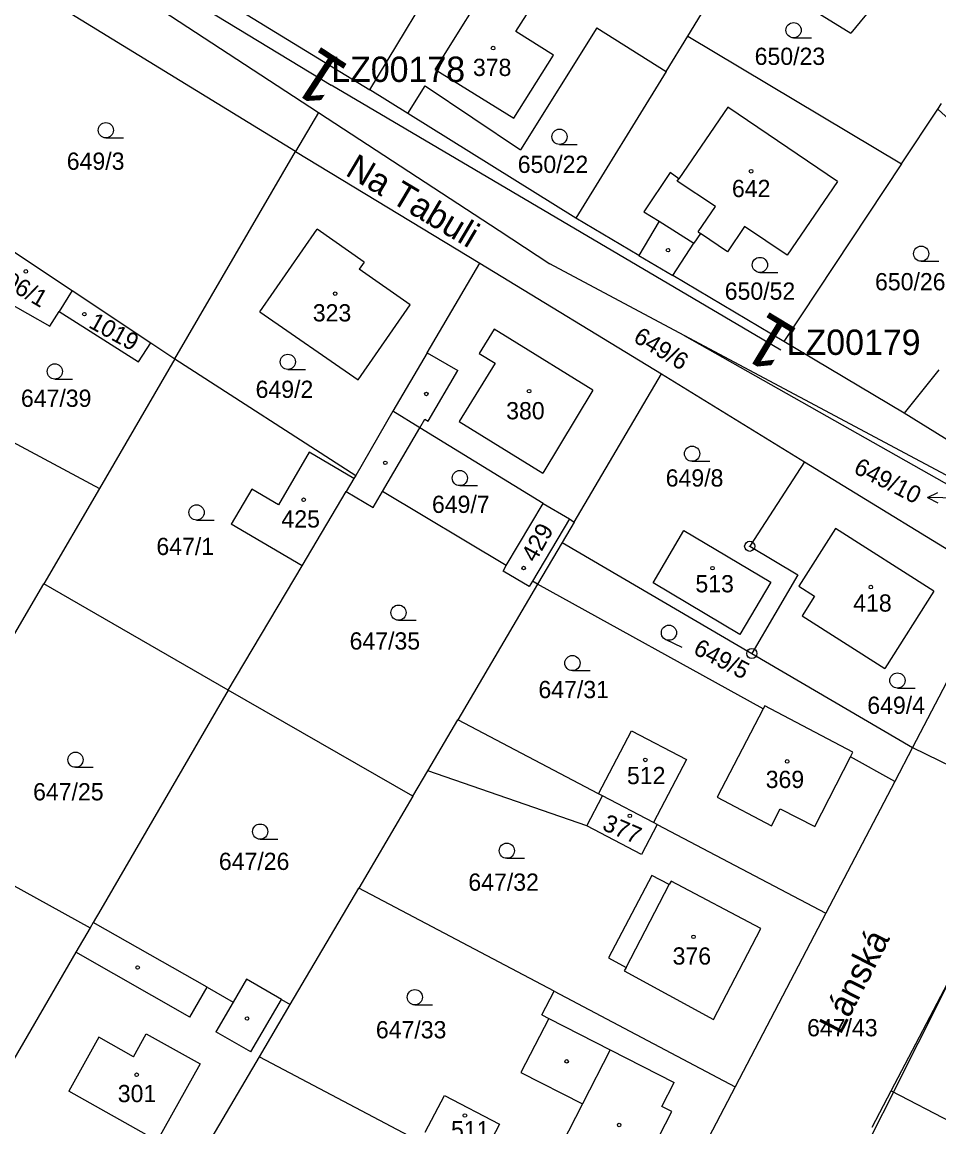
# Model space of a CAD drawing. Extents: x -738131 to -734179, y -1033447 to -1030078.
# Drawn here: x -735990.9 to -735900.5, y -1032576 to -1032467.1 of the extents above; entities that cross this region are included whole.
import ezdxf

# ---------------------------------------------------------------- set-up
doc = ezdxf.new("R2010")
doc.units = 0
for name, color, linetype in [('ftf_2010', 7, 'Continuous'), ('ftf_3010', 7, 'Continuous'), ('ftf_3010_ftf_3010_gtda_3015_gtda_3015_1', 7, 'Continuous'), ('ftf_nu', 7, 'Continuous'), ('Vrstva 1', 7, 'Continuous'), ('Vrstva 2', 7, 'Continuous'), ('Vrstva 3', 7, 'Continuous'), ('Vrstva 4', 7, 'Continuous'), ('Vrstva 5', 7, 'Continuous'), ('Vrstva 7', 7, 'Continuous'), ('Vrstva 8', 7, 'Continuous')]:
    doc.layers.add(name, color=color, linetype=linetype)

msp = doc.modelspace()

# ---------------------------------------------------------------- linework, layer by layer
at = {"layer": 'ftf_2010'}
for points in [[(-735998.88, -1032445.56), (-735998.88, -1032446.09), (-736000.43, -1032449.03), (-735960.4, -1032473.34)], [(-735916.05, -1032499.44), (-735960.4, -1032473.34)], [(-735895.6, -1032554), (-735909.49, -1032581.62)]]:
    msp.add_lwpolyline(points, dxfattribs=at)
at = {"layer": 'Vrstva 1'}
for points in [[(-736001.29, -1032450.11), (-735961.65, -1032476.02)], [(-735963.89, -1032479.87), (-736004.16, -1032455.17)], [(-735899.3, -1032456.19), (-735909.16, -1032468.19)], [(-735956.57, -1032473.77), (-735948.6, -1032460.55)], [(-735977.39, -1032461.05), (-735956.57, -1032473.77)], [(-735918.63, -1032462.31), (-735909.16, -1032468.19)], [(-735925.22, -1032468.51), (-735923.86, -1032466.3)], [(-735934.2, -1032467.66), (-735941.72, -1032479.7)], [(-735934.2, -1032467.66), (-735927.34, -1032471.97)], [(-735927.34, -1032471.97), (-735925.22, -1032468.51)], [(-735925.22, -1032468.51), (-735904.14, -1032481.08)], [(-735927.34, -1032471.97), (-735936.25, -1032486.44)], [(-735952.82, -1032476.11), (-735956.57, -1032473.77)], [(-735952.82, -1032476.11), (-735951.13, -1032473.4)], [(-735951.13, -1032473.4), (-735941.72, -1032479.7)], [(-735961.65, -1032476.02), (-735963.89, -1032479.87)], [(-735961.65, -1032476.02), (-735943.83, -1032487.67)], [(-735936.25, -1032486.44), (-735952.82, -1032476.11)], [(-735921.28, -1032475.49), (-735926.09, -1032482.55)], [(-735910.47, -1032482.83), (-735921.28, -1032475.49)], [(-735904.14, -1032481.08), (-735900.58, -1032475.7)], [(-735900.58, -1032475.7), (-735900.2, -1032475.13)], [(-735900.58, -1032475.7), (-735895.38, -1032480.43)], [(-735975.8, -1032500.31), (-735963.89, -1032479.87)], [(-735963.89, -1032479.87), (-735945.72, -1032490.89)], [(-735904.14, -1032481.08), (-735915.75, -1032498.6)], [(-735926.97, -1032481.94), (-735929.55, -1032485.8)], [(-735926.09, -1032482.55), (-735926.97, -1032481.94)], [(-735910.47, -1032482.83), (-735915.41, -1032490.1)], [(-735929.55, -1032485.8), (-735928.03, -1032486.75)], [(-735930.05, -1032490.12), (-735936.25, -1032486.44)], [(-735928.03, -1032486.75), (-735930.05, -1032490.12)], [(-735967.43, -1032495.67), (-735961.78, -1032487.53)], [(-735957.12, -1032490.76), (-735961.78, -1032487.53)], [(-735943.83, -1032487.67), (-735938.83, -1032490.94)], [(-735923.96, -1032487.95), (-735924.62, -1032488.91)], [(-735921.3, -1032489.77), (-735923.96, -1032487.95)], [(-735919.62, -1032487.26), (-735921.3, -1032489.77)], [(-735915.41, -1032490.1), (-735919.62, -1032487.26)], [(-735993.94, -1032488.26), (-735990.54, -1032490.52)], [(-735926.71, -1032492.09), (-735924.62, -1032488.91)], [(-735930.05, -1032490.12), (-735926.71, -1032492.09)], [(-735990.54, -1032490.52), (-735985.92, -1032493.57)], [(-735957.12, -1032490.76), (-735957.62, -1032491.48)], [(-735950.91, -1032499.7), (-735945.72, -1032490.89)], [(-735945.72, -1032490.89), (-735927.82, -1032501.78)], [(-735925.59, -1032497.99), (-735938.83, -1032490.94)], [(-735952.59, -1032494.97), (-735957.62, -1032491.48)], [(-735915.75, -1032498.6), (-735926.71, -1032492.09)], [(-735992.53, -1032494.58), (-735988.14, -1032497.07)], [(-735985.92, -1032493.57), (-735987.22, -1032495.63)], [(-735985.92, -1032493.57), (-735978.16, -1032498.72)], [(-735988.14, -1032497.07), (-735987.22, -1032495.63)], [(-735987.22, -1032495.63), (-735979.37, -1032500.6)], [(-735967.43, -1032495.67), (-735957.74, -1032502.39)], [(-735957.74, -1032502.39), (-735952.59, -1032494.97)], [(-735979.37, -1032500.6), (-735978.16, -1032498.72)], [(-735978.16, -1032498.72), (-735975.8, -1032500.31)], [(-735925.59, -1032497.99), (-735891.4, -1032517.34)], [(-735890.87, -1032516.5), (-735925.59, -1032497.99)], [(-735903.89, -1032505.65), (-735915.75, -1032498.6)], [(-735950.91, -1032499.7), (-735954.32, -1032505.48)], [(-735975.8, -1032500.31), (-735983.24, -1032513.09)], [(-735975.8, -1032500.31), (-735957.97, -1032511.8)], [(-735936.43, -1032516.41), (-735927.82, -1032501.78)], [(-735927.82, -1032501.78), (-735913.7, -1032510.45)], [(-735900.46, -1032501.38), (-735903.89, -1032505.65)], [(-735997.79, -1032505.3), (-735983.24, -1032513.09)], [(-735954.32, -1032505.48), (-735957.97, -1032511.8)], [(-735951.65, -1032507.12), (-735954.32, -1032505.48)], [(-735889.62, -1032514.52), (-735903.89, -1032505.65)], [(-735939.48, -1032514.57), (-735951.65, -1032507.12)], [(-735962.55, -1032509.52), (-735965.59, -1032514.69)], [(-735958.15, -1032512.1), (-735962.55, -1032509.52)], [(-735913.7, -1032510.45), (-735919.12, -1032518.79)], [(-735913.7, -1032510.45), (-735894.48, -1032522.24)], [(-735957.97, -1032511.8), (-735958.15, -1032512.1)], [(-735983.24, -1032513.09), (-735988.72, -1032522.5)], [(-735958.15, -1032512.1), (-735958.92, -1032513.4)], [(-735968.2, -1032513.15), (-735970.24, -1032516.61)], [(-735965.59, -1032514.69), (-735968.2, -1032513.15)], [(-735963.26, -1032520.72), (-735958.92, -1032513.4)], [(-735958.92, -1032513.4), (-735956.26, -1032514.96)], [(-735956.26, -1032514.96), (-735955.33, -1032513.38)], [(-735943.12, -1032520.68), (-735955.33, -1032513.38)], [(-735943.12, -1032520.68), (-735939.48, -1032514.57)], [(-735939.48, -1032514.57), (-735936.9, -1032516.09)], [(-735936.43, -1032516.41), (-735937.61, -1032518.41)], [(-735936.9, -1032516.09), (-735936.43, -1032516.41)], [(-735963.26, -1032520.72), (-735970.24, -1032516.61)], [(-735928.65, -1032522.38), (-735925.6, -1032517.24)], [(-735925.6, -1032517.24), (-735917.04, -1032522.33)], [(-735910.67, -1032517.05), (-735914.27, -1032522.72)], [(-735900.95, -1032523.22), (-735910.67, -1032517.05)], [(-735937.61, -1032518.41), (-735940.03, -1032522.53)], [(-735937.61, -1032518.41), (-735918.91, -1032529.36)], [(-735919.12, -1032518.79), (-735914.36, -1032521.61)], [(-735970.53, -1032532.97), (-735963.26, -1032520.72)], [(-735943.44, -1032521.23), (-735943.12, -1032520.68)], [(-735940.86, -1032522.75), (-735943.44, -1032521.23)], [(-735914.36, -1032521.61), (-735918.91, -1032529.36)], [(-735992.95, -1032529.75), (-735988.72, -1032522.5)], [(-735970.53, -1032532.97), (-735988.72, -1032522.5)], [(-735940.03, -1032522.53), (-735947.89, -1032535.89)], [(-735940.55, -1032522.22), (-735940.86, -1032522.75)], [(-735940.03, -1032522.53), (-735940.55, -1032522.22)], [(-735917.79, -1032534.8), (-735940.03, -1032522.53)], [(-735920.09, -1032527.47), (-735928.65, -1032522.38)], [(-735917.04, -1032522.33), (-735920.09, -1032527.47)], [(-735914.27, -1032522.72), (-735912.72, -1032523.71)], [(-735894.48, -1032522.24), (-735903.06, -1032538.63)], [(-735912.72, -1032523.71), (-735913.96, -1032525.64)], [(-735900.95, -1032523.22), (-735905.79, -1032530.85)], [(-735913.96, -1032525.64), (-735905.79, -1032530.85)], [(-735918.91, -1032529.36), (-735903.06, -1032538.63)], [(-735970.53, -1032532.97), (-735983.11, -1032554.59)], [(-735952.34, -1032543.44), (-735970.53, -1032532.97)], [(-735917.79, -1032534.8), (-735922.32, -1032543.53)], [(-735917.64, -1032534.52), (-735917.79, -1032534.8)], [(-735908.95, -1032539.07), (-735917.64, -1032534.52)], [(-735950.85, -1032540.92), (-735947.89, -1032535.89)], [(-735934.03, -1032543.18), (-735947.89, -1032535.89)], [(-735934.03, -1032543.18), (-735930.76, -1032536.97)], [(-735930.76, -1032536.97), (-735925.34, -1032539.82)], [(-735909.19, -1032539.55), (-735908.95, -1032539.07)], [(-735903.06, -1032538.63), (-735904.8, -1032541.97)], [(-735903.06, -1032538.63), (-735896.53, -1032541.81)], [(-735925.34, -1032539.82), (-735928.61, -1032546.03)], [(-735912.71, -1032546.42), (-735909.19, -1032539.55)], [(-735904.8, -1032541.97), (-735909.19, -1032539.55)], [(-735952.34, -1032543.44), (-735950.85, -1032540.92)], [(-735935.17, -1032546.35), (-735950.85, -1032540.92)], [(-735904.8, -1032541.97), (-735911.61, -1032554.97)], [(-735952.34, -1032543.44), (-735957.67, -1032552.5)], [(-735933.62, -1032543.39), (-735934.03, -1032543.18)], [(-735928.61, -1032546.03), (-735933.62, -1032543.39)], [(-735922.32, -1032543.53), (-735916.96, -1032546.34)], [(-735916.96, -1032546.34), (-735916.11, -1032544.68)], [(-735916.11, -1032544.68), (-735912.71, -1032546.42)], [(-736002.55, -1032546.24), (-735984.16, -1032556.39)], [(-735929.78, -1032549.17), (-735935.17, -1032546.35)], [(-735928.24, -1032546.23), (-735929.78, -1032549.17)], [(-735928.24, -1032546.23), (-735928.61, -1032546.03)], [(-735928.24, -1032546.23), (-735911.61, -1032554.97)], [(-735928.78, -1032551.24), (-735933.05, -1032559.36)], [(-735927.06, -1032552.14), (-735928.78, -1032551.24)], [(-735926.87, -1032551.79), (-735927.06, -1032552.14)], [(-735918.03, -1032556.46), (-735926.87, -1032551.79)], [(-735964.43, -1032563.97), (-735957.67, -1032552.5)], [(-735938.41, -1032562.66), (-735957.67, -1032552.5)], [(-735983.11, -1032554.59), (-735983.86, -1032555.88)], [(-735911.61, -1032554.97), (-735920.55, -1032572.07)], [(-735984.16, -1032556.39), (-735985.57, -1032558.82)], [(-735983.86, -1032555.88), (-735984.16, -1032556.39)], [(-735972.62, -1032562.25), (-735983.86, -1032555.88)], [(-735922.7, -1032565.43), (-735918.03, -1032556.46)], [(-735985.57, -1032558.82), (-735994.48, -1032574.13)], [(-735933.05, -1032559.36), (-735931.29, -1032560.31)], [(-735931.29, -1032560.31), (-735931.49, -1032560.66)], [(-735931.49, -1032560.66), (-735922.7, -1032565.43)], [(-735905.17, -1032572.46), (-735898.9, -1032560.5)], [(-735968.75, -1032561.47), (-735970.05, -1032563.72)], [(-735965.29, -1032563.47), (-735968.75, -1032561.47)], [(-735972.62, -1032562.25), (-735970.05, -1032563.72)], [(-735939.6, -1032564.98), (-735938.41, -1032562.66)], [(-735938.41, -1032562.66), (-735920.55, -1032572.07)], [(-735967.45, -1032569.11), (-735964.43, -1032563.97)], [(-735965.29, -1032563.47), (-735964.43, -1032563.97)], [(-735938.93, -1032565.33), (-735941.67, -1032570.66)], [(-735939.6, -1032564.98), (-735938.93, -1032565.33)], [(-735976.46, -1032584.42), (-735967.45, -1032569.11)], [(-735967.45, -1032569.11), (-735933.28, -1032587.17)], [(-735941.67, -1032570.66), (-735935.62, -1032573.77)], [(-735951.11, -1032576.56), (-735949.21, -1032572.93)], [(-735949.21, -1032572.93), (-735943.78, -1032575.77)], [(-735920.55, -1032572.07), (-735929.5, -1032589.17)], [(-735907.05, -1032576.05), (-735905.17, -1032572.46)], [(-735905.17, -1032572.46), (-735899.23, -1032575.58)], [(-735935.62, -1032573.77), (-735938.38, -1032579.15)], [(-735943.78, -1032575.77), (-735945.69, -1032579.42)]]:
    msp.add_lwpolyline(points, dxfattribs=at)
at = {"layer": 'Vrstva 3'}
for p, q in [((-735914.79, -1032468.66), (-735913.04, -1032468.66)), ((-735982.61, -1032478.52), (-735980.86, -1032478.52)), ((-735937.87, -1032479.16), (-735936.12, -1032479.16)), ((-735902.21, -1032490.69), (-735900.46, -1032490.69)), ((-735918.11, -1032491.8), (-735916.36, -1032491.8)), ((-735964.66, -1032501.35), (-735962.91, -1032501.35)), ((-735987.64, -1032502.3), (-735985.89, -1032502.3)), ((-735924.8, -1032510.41), (-735923.05, -1032510.41)), ((-735947.7, -1032512.81), (-735945.95, -1032512.81)), ((-735973.66, -1032516.2), (-735971.91, -1032516.2)), ((-735953.75, -1032526.08), (-735952, -1032526.08)), ((-735927.4, -1032527.98), (-735925.82, -1032528.73)), ((-735936.6, -1032531.05), (-735934.85, -1032531.05)), ((-735904.55, -1032532.77), (-735902.8, -1032532.77)), ((-735985.6, -1032540.58), (-735983.85, -1032540.58)), ((-735967.39, -1032547.67), (-735965.64, -1032547.67)), ((-735943.07, -1032549.55), (-735941.32, -1032549.55)), ((-735952.14, -1032564), (-735950.39, -1032564))]:
    msp.add_line(p, q, dxfattribs=at)
for centre in [(-735914.79, -1032467.91), (-735982.61, -1032477.77), (-735937.87, -1032478.41), (-735902.21, -1032489.94), (-735918.11, -1032491.05), (-735964.66, -1032500.6), (-735987.64, -1032501.55), (-735924.8, -1032509.66), (-735947.7, -1032512.06), (-735973.66, -1032515.45), (-735953.75, -1032525.33), (-735927.08, -1032527.31), (-735936.6, -1032530.3), (-735904.55, -1032532.02), (-735985.6, -1032539.83), (-735967.39, -1032546.92), (-735943.07, -1032548.8), (-735952.14, -1032563.25)]:
    msp.add_circle(centre, 0.75, dxfattribs=at)
at = {"layer": 'Vrstva 4'}
for points in [[(-735950.13, -1032471.78), (-735943.91, -1032461.81)], [(-735942.17, -1032468.04), (-735939.86, -1032464.35)], [(-735938.48, -1032470.36), (-735942.17, -1032468.04)], [(-735942.36, -1032476.58), (-735938.48, -1032470.36)], [(-735950.13, -1032471.78), (-735942.36, -1032476.58)], [(-735926.26, -1032482.79), (-735926.09, -1032482.55)], [(-735922.5, -1032485.3), (-735926.26, -1032482.79)], [(-735924.21, -1032487.79), (-735922.5, -1032485.3)], [(-735928.03, -1032486.75), (-735924.62, -1032488.91)], [(-735924.21, -1032487.79), (-735923.96, -1032487.95)], [(-735944.3, -1032497.37), (-735945.78, -1032499.77)], [(-735942.76, -1032498.34), (-735944.3, -1032497.37)], [(-735934.6, -1032503.39), (-735942.76, -1032498.34)], [(-735950.91, -1032499.7), (-735947.9, -1032501.47)], [(-735945.78, -1032499.77), (-735944.21, -1032500.73)], [(-735944.21, -1032500.73), (-735947.76, -1032506.49)], [(-735950.82, -1032506.44), (-735947.9, -1032501.47)], [(-735934.6, -1032503.39), (-735939.51, -1032511.58)], [(-735951.65, -1032507.12), (-735951.14, -1032506.25)], [(-735951.14, -1032506.25), (-735950.82, -1032506.44)], [(-735947.76, -1032506.49), (-735939.51, -1032511.58)], [(-735955.33, -1032513.38), (-735951.65, -1032507.12)], [(-735936.9, -1032516.09), (-735940.55, -1032522.22)], [(-735935.17, -1032546.35), (-735933.62, -1032543.39)], [(-735931.29, -1032560.31), (-735927.06, -1032552.14)], [(-735974.31, -1032565.21), (-735985.57, -1032558.82)], [(-735974.31, -1032565.21), (-735972.62, -1032562.25)], [(-735970.05, -1032563.72), (-735971.76, -1032566.66)], [(-735968.31, -1032568.62), (-735965.29, -1032563.47)], [(-735938.93, -1032565.33), (-735932.88, -1032568.44)], [(-735983.29, -1032567.2), (-735986.27, -1032572.52)], [(-735979.89, -1032569.11), (-735983.29, -1032567.2)], [(-735979.89, -1032569.11), (-735978.62, -1032566.84)], [(-735978.62, -1032566.84), (-735973.3, -1032569.82)], [(-735968.31, -1032568.62), (-735971.76, -1032566.66)], [(-735932.88, -1032568.44), (-735935.62, -1032573.77)], [(-735932.88, -1032568.44), (-735926.58, -1032571.67)], [(-735973.3, -1032569.82), (-735977.55, -1032577.41)], [(-735927.78, -1032574.01), (-735926.58, -1032571.67)], [(-735977.55, -1032577.41), (-735986.27, -1032572.52)], [(-735926.78, -1032574.52), (-735927.78, -1032574.01)], [(-735931.09, -1032582.9), (-735926.78, -1032574.52)]]:
    msp.add_lwpolyline(points, dxfattribs=at)
at = {"layer": 'Vrstva 5'}
for centre in [(-735944.42, -1032469.67), (-735918.98, -1032481.81), (-735927.17, -1032489.59), (-735990.5, -1032491.69), (-735959.99, -1032493.88), (-735984.72, -1032495.9), (-735940.87, -1032503.5), (-735951, -1032503.77), (-735955.05, -1032510.56), (-735963.1, -1032514.2), (-735941.41, -1032520.93), (-735922.79, -1032520.94), (-735907.17, -1032522.81), (-735929.41, -1032539.85), (-735915.42, -1032540), (-735930.94, -1032545.36), (-735924.66, -1032557.29), (-735979.47, -1032560.32), (-735968.68, -1032565.34), (-735937.16, -1032569.57), (-735979.57, -1032570.89), (-735947.2, -1032574.91), (-735931.99, -1032575.84)]:
    msp.add_circle(centre, 0.175, dxfattribs=at)
at = {"layer": 'Vrstva 7'}
for p, q in [((-735901.57, -1032513.97), (-735900.56, -1032513.49)), ((-735898.57, -1032514.04), (-735901.57, -1032513.97)), ((-735901.57, -1032513.97), (-735900.58, -1032514.49))]:
    msp.add_line(p, q, dxfattribs=at)
at = {"layer": 'Vrstva 8'}
for centre, radius in [((-735919.12, -1032518.79), 0.5), ((-735919.12, -1032518.79), 0.0303), ((-735918.91, -1032529.36), 0.5), ((-735918.91, -1032529.36), 0.0303)]:
    msp.add_circle(centre, radius, dxfattribs=at)

# ---------------------------------------------------------------- texts
at = {"layer": 'ftf_3010'}
for rotation, p in [(146.7928, (-735958.43, -1032471.52)), (148.8032, (-735914.15, -1032497.55))]:
    msp.add_text('1', height=5.2, rotation=rotation, dxfattribs=at).set_placement(p)
at = {"layer": 'ftf_3010_ftf_3010_gtda_3015_gtda_3015_1'}
for s, p in [('LZ00178', (-735960.38, -1032473.01)), ('LZ00179', (-735915.47, -1032499.92))]:
    msp.add_text(s, height=2.5, dxfattribs=at).set_placement(p)
at = {"layer": 'ftf_nu'}
for s, rotation, p in [('Na Tabuli', 329.3057, (-735959.1, -1032482.14)), ('Lánská', 62.9377, (-735910.16, -1032567.03))]:
    msp.add_text(s, height=2.5, rotation=rotation, dxfattribs=at).set_placement(p)
at = {"layer": 'Vrstva 2'}
for s, p in [('650/23', (-735918.63, -1032471.33)), ('378', (-735946.41, -1032472.42)), ('649/3', (-735986.46, -1032481.67)), ('650/22', (-735941.99, -1032481.98)), ('642', (-735920.87, -1032484.36)), ('650/26', (-735906.76, -1032493.55)), ('650/52', (-735921.58, -1032494.48)), ('323', (-735962.2, -1032496.62)), ('647/39', (-735990.98, -1032505.04)), ('649/2', (-735967.84, -1032504.16)), ('380', (-735943.13, -1032506.27)), ('649/8', (-735927.4, -1032512.9)), ('649/7', (-735950.45, -1032515.5)), ('425', (-735965.29, -1032516.94)), ('647/1', (-735977.62, -1032519.65)), ('513', (-735924.47, -1032523.33)), ('418', (-735908.91, -1032525.23)), ('647/35', (-735958.57, -1032528.97)), ('647/31', (-735939.95, -1032533.76)), ('649/4', (-735907.52, -1032535.31)), ('512', (-735931.22, -1032542.24)), ('369', (-735917.54, -1032542.62)), ('647/25', (-735989.78, -1032543.84)), ('647/26', (-735971.46, -1032550.7)), ('647/32', (-735946.86, -1032552.75)), ('376', (-735926.72, -1032560.03)), ('647/43', (-735913.46, -1032567.1)), ('647/33', (-735955.98, -1032567.3)), ('301', (-735981.43, -1032573.59)), ('511', (-735948.57, -1032577.16))]:
    msp.add_text(s, height=1.7, dxfattribs=at).set_placement(p)
for s, rotation, p in [('506/1', 329.8255, (-735993.93, -1032492.45)), ('1019', 331.2202, (-735984.41, -1032497.15)), ('649/6', 328.6663, (-735930.7, -1032498.54)), ('429', 60.9062, (-735940.25, -1032520.47)), ('649/5', 332.6318, (-735924.79, -1032529.34)), ('377', 336.7787, (-735933.76, -1032546.7))]:
    msp.add_text(s, height=1.7, rotation=rotation, dxfattribs=at).set_placement(p)
at = {"layer": 'Vrstva 7'}
msp.add_text('649/10', height=1.7, rotation=333.0939, dxfattribs=at).set_placement((-735908.98, -1032511.51))

doc.saveas('drawing.dxf')
